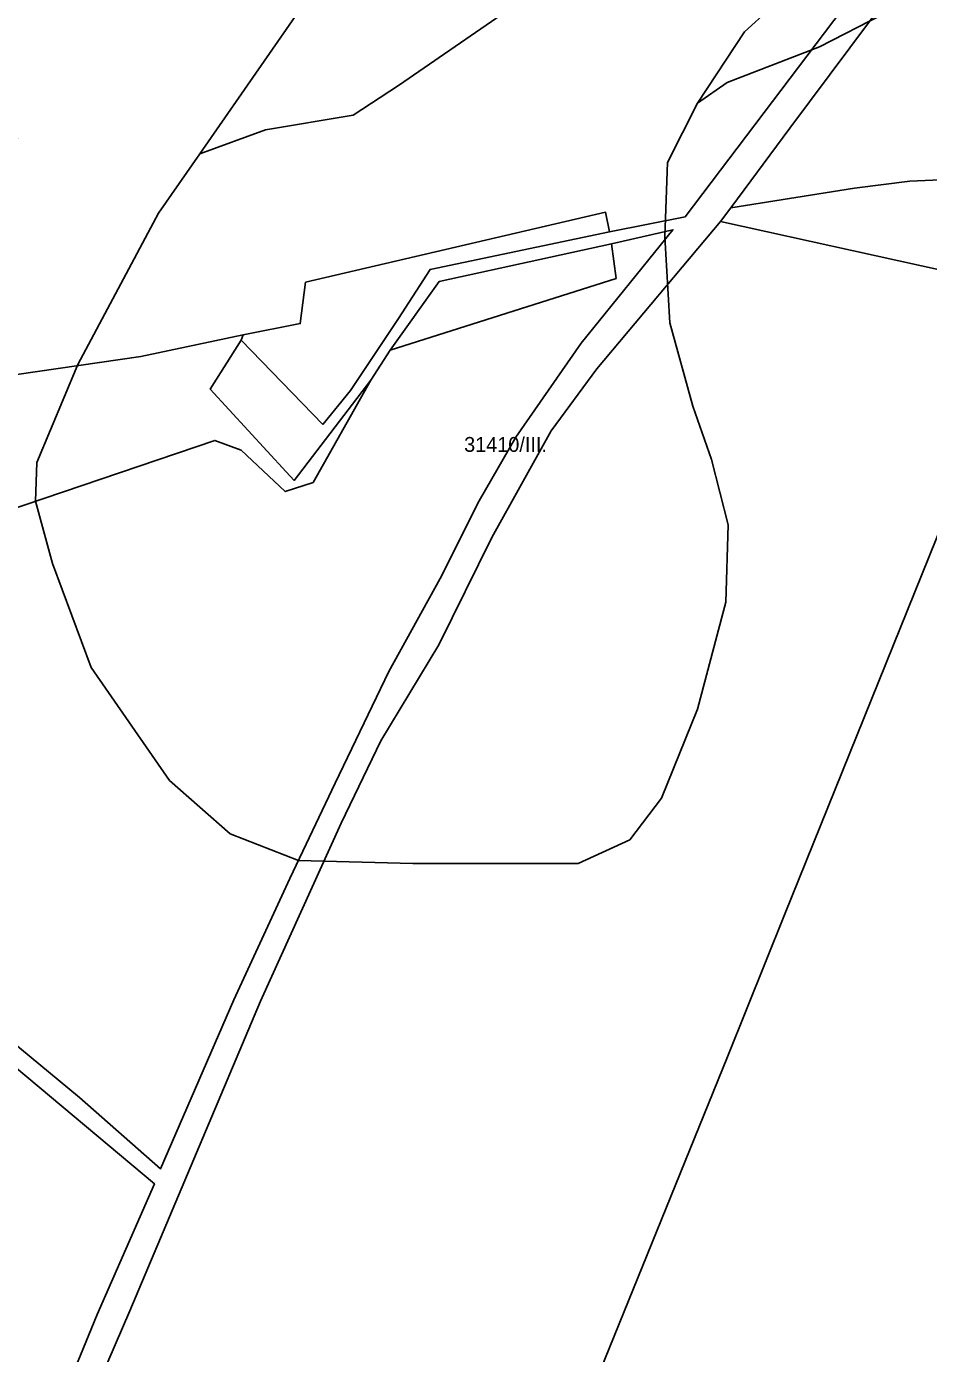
# Model space of a CAD drawing. Extents: x -532083 to -529270, y -1180561 to -1176456.
# Drawn here: x -530947.6 to -530643.9, y -1179426.9 to -1178980.2 of the extents above; entities that cross this region are included whole.
import ezdxf

# ---------------------------------------------------------------- set-up
doc = ezdxf.new("R2010")
doc.units = 0
for name, color, linetype in [('95560013', 7, 'Continuous'), ('95620013', 7, 'Continuous'), ('95660013', 7, 'Continuous')]:
    doc.layers.add(name, color=color, linetype=linetype)

msp = doc.modelspace()

# ---------------------------------------------------------------- linework, layer by layer
at = {"layer": '95560013'}
for points in [[(-530321.3073, -1178925.52945), (-530332.4003, -1178981.99545), (-530345.5483, -1179043.40645), (-530391.6263, -1179044.11145), (-530428.5473, -1179045.37145), (-530438.5943, -1179045.37145), (-530467.4773, -1179035.79645), (-530491.0873, -1179028.23845), (-530503.3233, -1179026.20245), (-530514.7293, -1179024.56745), (-530519.2893, -1179017.55745), (-530527.3723, -1179011.89745), (-530532.2523, -1179010.97945), (-530551.6213, -1179011.13245), (-530578.9203, -1179012.96845), (-530613.2353, -1179015.72145), (-530611.8623, -1179024.74845), (-530625.1313, -1179025.05445), (-530629.4813, -1179031.33945), (-530650.1973, -1179032.27345), (-530668.8183, -1179034.60845), (-530710.4553, -1179041.28045), (-530690.5463, -1179014.35945), (-530643.5763, -1178951.29245)], [(-530658.2913, -1178954.87545), (-530725.8063, -1179044.23145), (-530751.3463, -1179049.30845), (-530752.6093, -1179042.71945), (-530853.6623, -1179066.28845), (-530855.4313, -1179080.22645), (-530874.6313, -1179084.02845), (-530909.1583, -1179091.26445), (-530950.9083, -1179097.29245), (-530967.9883, -1179100.78345), (-530973.6643, -1179053.04545), (-530974.3083, -1179027.41445), (-530955.1983, -1179018.79845), (-530950.6093, -1179017.85245), (-530974.5343, -1178986.22345), (-530983.6223, -1178955.52445)], [(-530982.2063, -1179740.95245), (-531002.4393, -1179671.14445), (-531008.2583, -1179642.17845), (-530991.3113, -1179601.48545), (-530965.1553, -1179539.63945), (-530922.7333, -1179435.44145), (-530912.8693, -1179412.60445), (-530868.8573, -1179308.31745), (-530841.6463, -1179248.37045), (-530828.3473, -1179220.63445), (-530808.7483, -1179188.33545), (-530790.8993, -1179152.17445), (-530770.9513, -1179116.36445), (-530755.5653, -1179095.46845), (-530713.8673, -1179045.84445), (-530638.6183, -1179062.40745)], [(-530967.3553, -1179147.74245), (-530884.2313, -1179119.50845), (-530875.3893, -1179122.80345), (-530860.4833, -1179136.74145), (-530851.1363, -1179133.70045), (-530831.6833, -1179099.23445), (-530825.1153, -1179089.09645), (-530749.0723, -1179065.02045), (-530750.5883, -1179053.36345), (-530729.9173, -1179048.62945), (-530760.8843, -1179086.84245), (-530782.8073, -1179118.45745), (-530795.1393, -1179139.90045), (-530808.3133, -1179165.98845), (-530825.5873, -1179197.34445), (-530843.6833, -1179234.88845), (-530858.9003, -1179267.06845), (-530877.8193, -1179307.91345), (-530902.4513, -1179364.73245), (-530929.8263, -1179340.76445), (-530953.2153, -1179321.37245)], [(-530624.0833, -1179110.25145), (-530692.4043, -1179279.29745), (-530711.6183, -1179327.08245), (-530752.8893, -1179428.87345), (-530780.3383, -1179501.33545), (-530792.0203, -1179529.85045), (-530840.3343, -1179531.93145), (-530866.4173, -1179584.85745), (-530883.0153, -1179626.18745), (-530904.8823, -1179682.75545), (-530925.0953, -1179729.23645), (-530887.7793, -1179774.78045), (-530858.8613, -1179812.72545), (-530824.8703, -1179874.67145), (-530797.3943, -1179923.83045), (-530786.3453, -1179940.81745), (-530768.2873, -1179960.35245), (-530749.8763, -1179974.91445), (-530718.0113, -1179997.29145), (-530679.7723, -1180020.73345), (-530652.1383, -1180035.12045), (-530616.5163, -1180051.56345)], [(-531116.1203, -1179467.89045), (-531080.0903, -1179423.57845), (-531074.3173, -1179416.15945), (-531069.7743, -1179411.12345), (-531065.4713, -1179405.36745), (-531061.1673, -1179400.09145), (-531056.6253, -1179394.57545), (-531050.4083, -1179387.38045), (-531045.3873, -1179381.14545), (-531041.8013, -1179376.82845), (-531031.2813, -1179360.99945), (-531026.2603, -1179354.76445), (-531019.8023, -1179307.72745), (-531018.8473, -1179297.67245), (-531015.2683, -1179296.47545), (-531015.2793, -1179291.70545), (-531004.4833, -1179286.66745), (-530997.3683, -1179292.40545), (-530955.1243, -1179327.35845), (-530904.5683, -1179369.77645), (-530923.8833, -1179413.83845), (-530953.9483, -1179487.19045)]]:
    msp.add_lwpolyline(points, dxfattribs=at)
for points in [[(-530847.8523, -1179114.18645), (-530875.3893, -1179085.80245), (-530874.6313, -1179084.02845), (-530855.4313, -1179080.22645), (-530853.6623, -1179066.28845), (-530752.6093, -1179042.71945), (-530751.3463, -1179049.30845), (-530811.7253, -1179061.97945), (-530822.3363, -1179078.45245), (-530838.5043, -1179102.78245)], [(-530749.0723, -1179065.02045), (-530825.1153, -1179089.09645), (-530808.6943, -1179066.03445), (-530750.5883, -1179053.36345)], [(-530884.2313, -1179119.50845), (-530967.3553, -1179147.74245), (-530967.0393, -1179125.84945), (-530967.9883, -1179100.78345), (-530950.9083, -1179097.29245), (-530909.1583, -1179091.26445), (-530874.6313, -1179084.02845), (-530875.3893, -1179085.80245), (-530885.7473, -1179102.27545), (-530860.2313, -1179130.15245), (-530857.4993, -1179133.02145), (-530831.6833, -1179099.23445), (-530851.1363, -1179133.70045), (-530860.4833, -1179136.74145), (-530875.3893, -1179122.80345)]]:
    msp.add_lwpolyline(points, close=True, dxfattribs=at)
at = {"layer": '95620013'}
for points in [[(-530638.6183, -1179062.40745), (-530713.8673, -1179045.84445), (-530710.4553, -1179041.28045), (-530668.8183, -1179034.60845), (-530650.1973, -1179032.27345), (-530629.4813, -1179031.33945)], [(-530638.1853, -1179917.86845), (-530656.2083, -1179951.88945), (-530671.4873, -1179971.33845), (-530710.5303, -1179971.53645), (-530738.3333, -1179952.54645), (-530784.2593, -1179922.01445), (-530802.5813, -1179881.01145), (-530821.6083, -1179839.30245), (-530887.7793, -1179774.78045), (-530925.0953, -1179729.23645), (-530904.8823, -1179682.75545), (-530883.0153, -1179626.18745), (-530866.4173, -1179584.85745), (-530840.3343, -1179531.93145), (-530792.0203, -1179529.85045), (-530780.3383, -1179501.33545), (-530752.8893, -1179428.87345), (-530711.6183, -1179327.08245), (-530692.4043, -1179279.29745), (-530624.0833, -1179110.25145)]]:
    msp.add_lwpolyline(points, dxfattribs=at)
at = {"layer": '95660013'}
for points in [[(-530844.1253, -1178958.00045), (-530889.3123, -1179023.00045), (-530903.1873, -1179043.00045), (-530930.3123, -1179094.00045), (-530944.1873, -1179127.00045), (-530944.6253, -1179140.00045), (-530938.8753, -1179161.00045), (-530925.8123, -1179196.00045), (-530899.5003, -1179234.00045), (-530879.0003, -1179252.00045), (-530856.0003, -1179261.00045), (-530817.5003, -1179262.00045), (-530761.8123, -1179262.00045), (-530744.5003, -1179254.00045), (-530733.8123, -1179240.00045), (-530721.6253, -1179210.00045), (-530712.1253, -1179174.00045), (-530711.3123, -1179148.00045), (-530717.0003, -1179126.00045), (-530723.1873, -1179108.00045), (-530731.0003, -1179080.00045), (-530732.6253, -1179051.00045), (-530731.8123, -1179026.00045), (-530721.6253, -1179006.00045), (-530711.6873, -1178999.00045), (-530680.6253, -1178987.00045), (-530659.1873, -1178976.00045)], [(-530680.6253, -1178959.00045), (-530705.8753, -1178982.00045), (-530721.6253, -1179006.00045), (-530731.8123, -1179026.00045), (-530732.6253, -1179051.00045), (-530731.0003, -1179080.00045), (-530723.1873, -1179108.00045), (-530717.0003, -1179126.00045), (-530711.3123, -1179148.00045), (-530712.1253, -1179174.00045), (-530721.6253, -1179210.00045), (-530733.8123, -1179240.00045), (-530744.5003, -1179254.00045), (-530761.8123, -1179262.00045), (-530817.5003, -1179262.00045), (-530856.0003, -1179261.00045), (-530879.0003, -1179252.00045), (-530899.5003, -1179234.00045), (-530925.8123, -1179196.00045), (-530938.8753, -1179161.00045), (-530944.6253, -1179140.00045), (-530944.1873, -1179127.00045), (-530930.3123, -1179094.00045), (-530903.1873, -1179043.00045), (-530889.3123, -1179023.00045), (-530867.1253, -1179015.00045), (-530837.6253, -1179010.00045), (-530822.3753, -1179000.00045), (-530777.3123, -1178969.00045)], [(-530777.3123, -1178969.00045), (-530822.3753, -1179000.00045), (-530837.6253, -1179010.00045), (-530867.1253, -1179015.00045), (-530889.3123, -1179023.00045), (-530844.1253, -1178958.00045)], [(-530659.1873, -1178976.00045), (-530680.6253, -1178987.00045), (-530711.6873, -1178999.00045), (-530721.6253, -1179006.00045), (-530705.8753, -1178982.00045), (-530680.6253, -1178959.00045)], [(-530638.6183, -1179062.40745), (-530713.8673, -1179045.84445), (-530710.4553, -1179041.28045), (-530668.8183, -1179034.60845), (-530650.1973, -1179032.27345), (-530629.4813, -1179031.33945)], [(-530629.4813, -1179031.33945), (-530650.1973, -1179032.27345), (-530668.8183, -1179034.60845), (-530710.4553, -1179041.28045), (-530713.8673, -1179045.84445), (-530638.6183, -1179062.40745)], [(-530638.1853, -1179917.86845), (-530656.2083, -1179951.88945), (-530671.4873, -1179971.33845), (-530690.4433, -1179971.43445), (-530710.5303, -1179971.53645), (-530738.3333, -1179952.54645), (-530784.2593, -1179922.01445), (-530802.5813, -1179881.01145), (-530821.6083, -1179839.30245), (-530887.7793, -1179774.78045), (-530925.0953, -1179729.23645), (-530904.8823, -1179682.75545), (-530901.7523, -1179674.65945), (-530883.0153, -1179626.18745), (-530866.4173, -1179584.85745), (-530840.3343, -1179531.93145), (-530792.0203, -1179529.85045), (-530780.3383, -1179501.33545), (-530752.8893, -1179428.87345), (-530711.6183, -1179327.08245), (-530692.4043, -1179279.29745), (-530624.0833, -1179110.25145)], [(-530624.0833, -1179110.25145), (-530692.4043, -1179279.29745), (-530711.6183, -1179327.08245), (-530752.8893, -1179428.87345)]]:
    msp.add_lwpolyline(points, dxfattribs=at)

# ---------------------------------------------------------------- texts
msp.add_text('31410/III.', height=5, rotation=0, dxfattribs=at).set_placement((-530800.2503, -1179123.39027))

doc.saveas('drawing.dxf')
